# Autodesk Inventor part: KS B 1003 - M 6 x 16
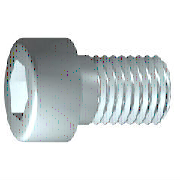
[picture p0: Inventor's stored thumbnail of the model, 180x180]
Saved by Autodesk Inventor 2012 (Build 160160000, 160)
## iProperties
Created: 2009-02
Part Number: KS B 1003 - M 6 x 16
Material: Steel, Mild
Description: 6각머리 태핑 나사
Document SubType Name: Modeling
Standard: KS B 1003
Designer: KYOUNG IL JANG
Standards Organization: KS
Language: ko-KR
Size Designation: M 6 x 16
Categories: <MemberInstance><Categories><Category DisplayName="조임쇠" InternalName="e4da775c-781d-43d5-af7c-5136215cf5a6" Mnemonic="FSTN"><Category DisplayName="볼트" InternalN
Density: 1 g/cm^3
Company: 한국ATC센터
IsCustomPart: 0
Author: KYOUNG IL JANG
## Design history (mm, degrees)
workplane "Work Plane1"
fillet "Fillet2" dims "d30" = 0.1 (= R)
revolve "본체" stored, may be unused: angle "d10" = 90 deg
sketch "스케치2"
  geometry: L1 (0, -7)-(0, 7) reference; L2 (-7, 0)-(7, 0) reference; L3 (2.887, 0)-(1.443, -2.5); L4 (1.443, -2.5)-(-1.443, -2.5); L5 (-1.443, -2.5)-(-2.887, 0); L6 (-2.887, 0)-(-1.443, 2.5); L7 (-1.443, 2.5)-(1.443, 2.5); L8 (1.443, 2.5)-(2.887, 0); 2 further points
  constraints: 12 end point, 1 coincident, 1 horizontal alignment, 1 point on line, 12 other
extrude "슬롯" join sketch "스케치2" stored distance "d11" = 10; taper "d12" = 0 deg
body "Solid1"
fillet "모깎기1" dims "d17" = 0.6 (= RR)
feature "스레드" dims "d13" = 13.5 (= GEL), "d14" = 0
chamfer "모따기1" distance "d15" = 0.61345 (= -0.5 x SPD + 0.5 x GD); stored, may be unused: second distance "d16" = 0.61345 (= GUL), angle "d27" = 45 deg
sketch "스케치1"
  geometry: L1 (-1.333, 0)-(16, 0); L2 (16, 0)-(16, 3); L3 (16, 3)-(2.5, 3); L4 (2.5, 3)-(1.886, 3); L5 (1.886, 3)-(0, 3); L6 (0, 3)-(0, 5); L7 (0, 5)-(-6, 5); L8 (-6, 5)-(-6, 2.887); L9 (-6, 2.887)-(-3, 2.887); L10 (-3, 2.887)-(-1.333, 0); L11 (-10.4, 0)-(20.4, 0) reference; L12 (0, -1)-(0, 6) reference; L13 (2.5, 3)-(0, 3)
  constraints: 22 end point, 6 parallel, 2 collinear, 2 perpendicular, 1 horizontal, 1 point on line
  dimensions: "d1" = 13.5 distance from line of L3.end L2 (= GEL); "d2" = 0.61355 distance of L4.end L3.end (computed from GAL); "d3" = 6 distance between parallel lines of L8 L6 (= KOH); "d4" = 3 distance of L8.end L9.end (= INTI); "d5" = 60 deg angle of L10 L1; "d6" = 6 diameter of L3 L1 (= GD); "d7" = 6 diameter of L5 L1 (= BDM); "d8" = 5.7735 diameter of L9 L1 (= 1.1547 x SW); "d9" = 10 diameter of L7 L1 (= KOD); "d26" = 16 distance between parallel lines of L12 L2 (= NLG)
other parameters: "GD" = 6 (= NND) [user parameter; used in 2 equation terms], "NLG" = 16 [user parameter; used in 1 equation term], "GEL" = 13.5 [user parameter; used in 2 equation terms], "KOD" = 10 [user parameter; used in 1 equation term], "KOH" = 6 [user parameter; used in 1 equation term], "INTI" = 3 [user parameter; used in 1 equation term], "GAL" = 0.61345 (= 0.61345 x PTC) [user parameter; used in 1 equation term], "GUL" = 0.61345 (= 0.61345 x PTC) [user parameter; used in 1 equation term], "BDM" = 6 (= NND) [user parameter; used in 1 equation term], "SW" = 5 [user parameter; used in 2 equation terms], "RR" = 0.6 [user parameter; used in 1 equation term], "SPD" = 4.7731 (= NND - 1.2269 x PTC) [user parameter; used in 1 equation term], "d19" = 0, "d28" = 0, "d29" = 0, "R" = 0.1 [user parameter; used in 1 equation term], "PHH" = 0.25 [user parameter], "GD1" = 4.7731 (= THREADDIA - 1.2269 x PTC) [user parameter], "THREADDIA" = 6 [user parameter; used in 1 equation term], "FAWI" = 45 deg [user parameter], "PTC" = 1 [user parameter; used in 5 equation terms], "NND" = 6 [user parameter; used in 3 equation terms], "TOA" = 30 deg [user parameter], "E0" = 5.775 (= 1.155 x SW) [user parameter]
